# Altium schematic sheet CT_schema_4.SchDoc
size 199 x 169 mm
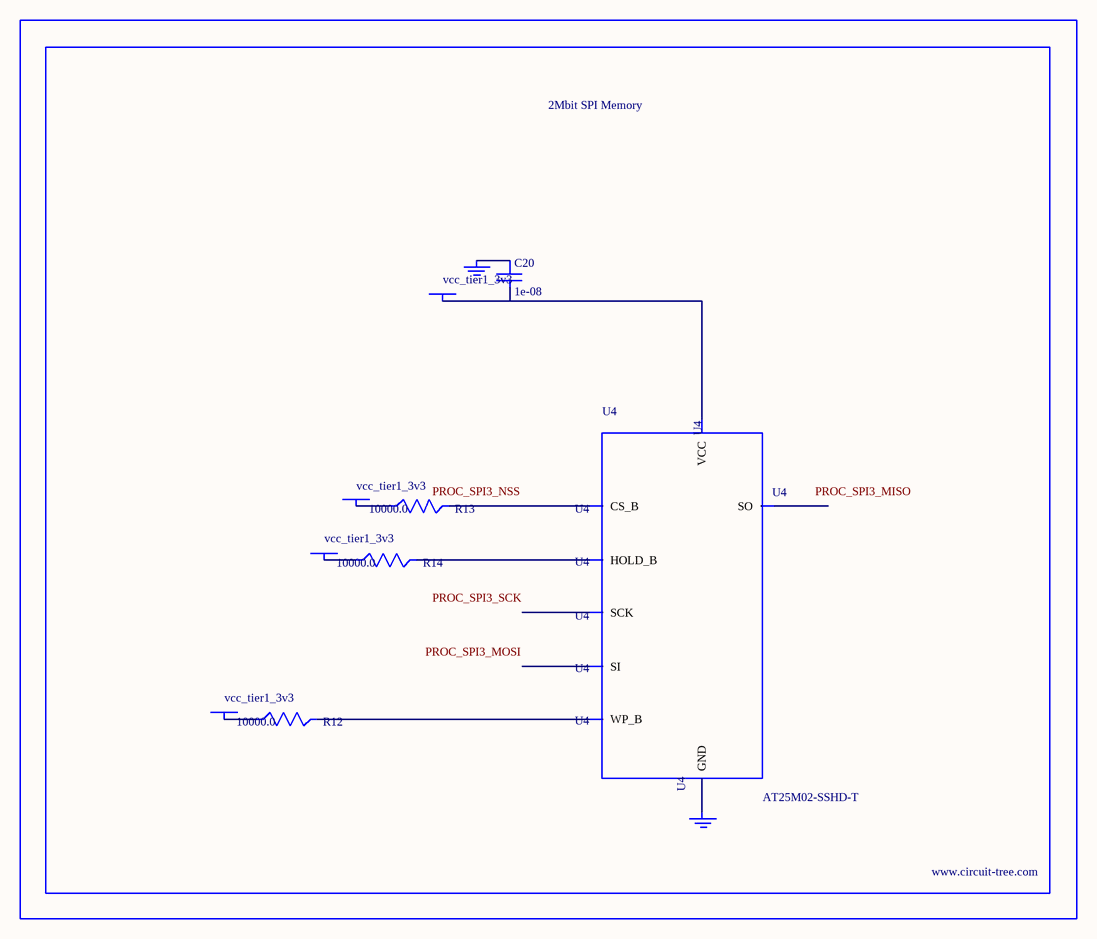
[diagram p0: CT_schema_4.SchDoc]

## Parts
BORDER3  (no value)
C20  1e-08  [C0402]
GND_INSTANCE_3_0  (no value)
GND_INSTANCE_3_1  (no value)
POWER_INSTANCE_3_0  vcc_tier1_3v3
POWER_INSTANCE_3_1  vcc_tier1_3v3
POWER_INSTANCE_3_2  vcc_tier1_3v3
POWER_INSTANCE_3_3  vcc_tier1_3v3
R12  10000.0  [R0603]
R13  10000.0  [R0603]
R14  10000.0  [R0603]
U4  AT25M02-SSHD-T  [SOIC-8]

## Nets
NetC20_1: C20.1 GND_INSTANCE_3_0.0(GND)
NetC20_2: C20.2 POWER_INSTANCE_3_3.0(PWR) U4.8(VCC)
NetGND_INSTANCE_3_1_0: GND_INSTANCE_3_1.0(GND) U4.4(GND)
NetPOWER_INSTANCE_3_0_0: POWER_INSTANCE_3_0.0(PWR) R13.1
NetPOWER_INSTANCE_3_1_0: POWER_INSTANCE_3_1.0(PWR) R12.1
NetPOWER_INSTANCE_3_2_0: POWER_INSTANCE_3_2.0(PWR) R14.1
NetR12_2: R12.2 U4.3(WP_B)
NetR13_2: R13.2 U4.1(CS_B)
NetR14_2: R14.2 U4.7(HOLD_B)

Not connected (* = marked no-connect by the designer): U4 2(SO) 5(SI) 6(SCK)

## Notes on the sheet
- Labels drawn without touching a wire or pin: PROC_SPI3_MISO, PROC_SPI3_MOSI, PROC_SPI3_NSS, PROC_SPI3_SCK

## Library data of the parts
BORDER3 = BORDER_PAGE3
C20 = C0402C103K3RAC
GND_INSTANCE_3_0 GND_INSTANCE_3_1 = GND
POWER_INSTANCE_3_0-POWER_INSTANCE_3_3 = PWR
R12-R14 = RC0603JR-0710KL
